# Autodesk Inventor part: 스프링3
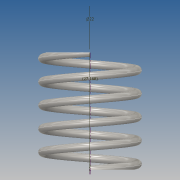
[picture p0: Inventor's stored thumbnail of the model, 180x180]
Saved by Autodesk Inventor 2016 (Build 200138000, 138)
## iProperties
Created: 2016-01
Part Number: 스프링3
Material: 스테인레스 스틸
Document SubType Name: Modeling
Designer: Administrator
Density: 8 g/cm^3
Appearance: 반연마
Mass: 8.55991 g
Surface Area: 21.737 cm^2
Volume: 1.06999 cm^3
Author: Administrator
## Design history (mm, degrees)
sketch "스케치1"
  geometry: L1 (0, 0)-(11, 0); L2 (11, 0)-(11, 27.168); L3 (11, 27.168)-(0, 27.168); L4 (0, 27.168)-(0, 0); C1 r 1 at (11, 0)
  constraints: 8 end point, 2 parallel, 1 centre point, 1 coincident, 1 horizontal, 1 perpendicular
  dimensions: "d0" = 2 diameter of C1; "d1" = 27.16848 distance of L1.end L2.end (derived); "d2" = 22 diameter of L2 L4
feature "코일1" pitch "d3" = 10; turns "d5" = 5; dims "d4" = 27.16848 (= d1), "d6" = 0, angle "d7" = 90 deg, angle "d8" = 90 deg, "d9" = 0, "d10" = 0
sketch "스케치2"
  geometry: L1 (5.3, 0)-(-21.597, 0); L2 (-21.597, 0)-(-21.597, -10.619); L3 (-21.597, -10.619)-(5.3, -10.619); L4 (5.3, -10.619)-(5.3, 0); 3 further points
  constraints: 8 end point, 2 parallel, 1 horizontal, 1 horizontal alignment, 1 perpendicular, 1 point on line
extrude "돌출1" cut sketch "스케치2" stored distance "d11" = 0; taper "d12" = 0 deg
sketch "스케치3"
  geometry: L1 (-4.261, 0)-(22.454, 0); L2 (22.454, 0)-(22.454, 6.999); L3 (22.454, 6.999)-(-4.261, 6.999); L4 (-4.261, 6.999)-(-4.261, 0); 3 further points
  constraints: 8 end point, 2 parallel, 1 horizontal, 1 horizontal alignment, 1 perpendicular, 1 point on line
extrude "돌출2" cut sketch "스케치3" stored distance "d13" = 0; taper "d14" = 0 deg
node "솔리드1"
